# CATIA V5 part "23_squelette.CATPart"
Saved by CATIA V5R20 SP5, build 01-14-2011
Part number: 23_squelette
Publications: "Plan.1", "Plan yz"
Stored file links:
  C:\Documents and Settings\anizard\Bureau\13\23_squelette.CATPart
  C:\Documents and Settings\anizard\Bureau\13\anizard.CATProduct
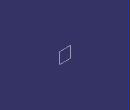
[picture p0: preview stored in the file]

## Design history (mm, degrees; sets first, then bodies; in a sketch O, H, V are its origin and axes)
Parameters
  epaisseur = 12 mm
Set1
  Plane1: linked copy from another document
Body1 (main body)
  Plane2: type Offset, RefPlane Plane1, Offset 12 {= epaisseur}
